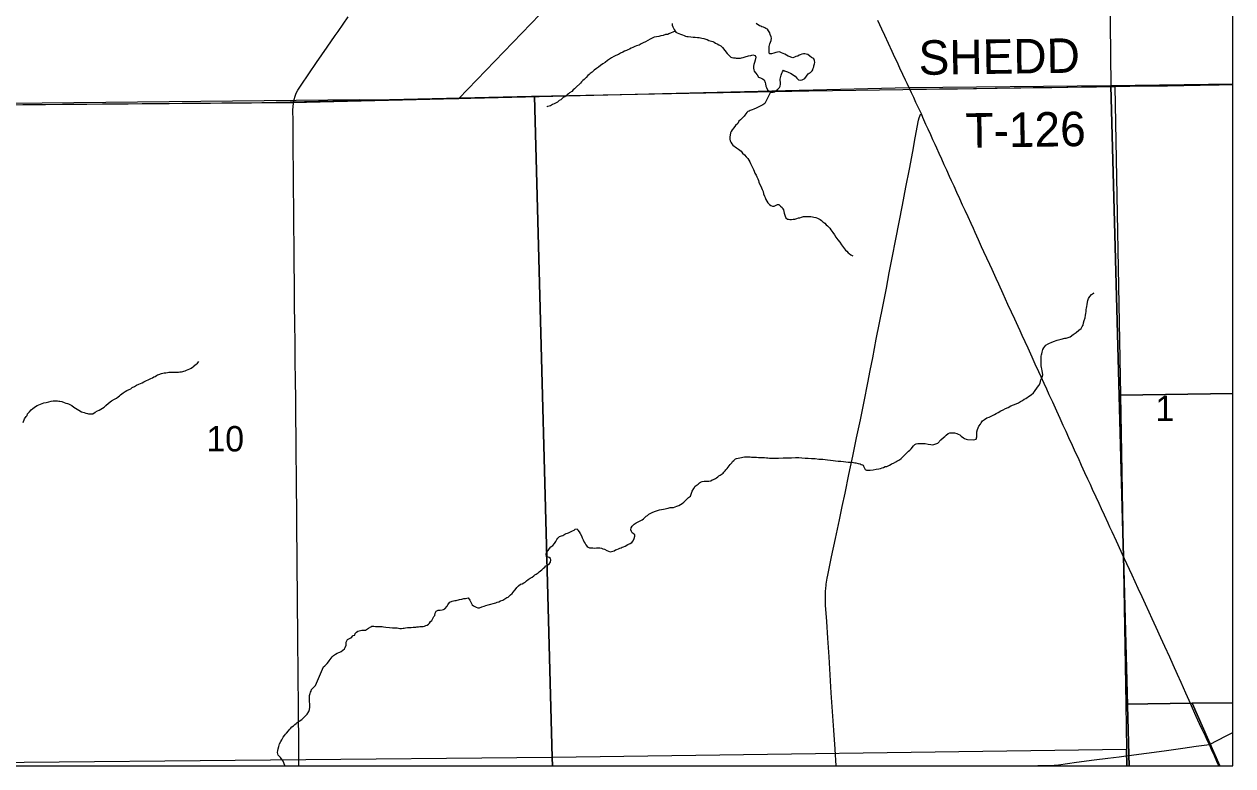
# Model space of a CAD drawing. Extents: x 103424 to 290657, y 38711 to 110967.
# Drawn here: x 165088 to 175680, y 38711 to 45205 of the extents above; entities that cross this region are included whole.
import ezdxf

# ---------------------------------------------------------------- set-up
doc = ezdxf.new("R2010")
doc.units = 0
for name, color, linetype in [('GM_X_Corporation', 7, 'Continuous'), ('GM_X_County_Road', 7, 'Continuous'), ('GM_X_Minor_Lake', 7, 'Continuous'), ('GM_X_Minor_River', 7, 'Continuous'), ('GM_X_Rail_Line', 7, 'Continuous'), ('GM_X_Section_Text', 7, 'Continuous'), ('GM_X_State_Route', 7, 'Continuous'), ('GM_X_Township_Road', 7, 'Continuous'), ('GM_X_Township_Road_Text', 7, 'Continuous')]:
    doc.layers.add(name, color=color, linetype=linetype)

msp = doc.modelspace()

# ---------------------------------------------------------------- linework, layer by layer
at = {"layer": 'GM_X_Corporation'}
for points in [[(103424, 96535), (103424, 38711), (175680, 38711), (175680, 110967), (119699, 110967), (119717, 106543), (119720, 106323), (119721, 106006), (119710, 99446), (119706, 99064), (119664, 96690), (117026, 96688), (115542, 96665), (105082, 96575)], [(175680, 44681), (175680, 72246), (175616, 72243), (174070, 72209), (174125, 69464), (174129, 69223), (174137, 68978), (174141, 68791), (174153, 68331), (174162, 67903), (174163, 67851), (174375, 58453), (174464, 53422), (174471, 52952), (174477, 52329), (174484, 51788), (174488, 51508), (174502, 50651), (174515, 49999), (174519, 49484), (174525, 49008), (174531, 48282), (174580, 47395), (174610, 44665)], [(149533, 38711), (174770, 38711), (174768, 38806), (174722, 40540), (174610, 44665), (172843, 44649), (172841, 44649), (167442, 44516), (162024, 44473), (156824, 44364), (149451, 44181), (149476, 42605), (149528, 39851)], [(174646, 44661), (174695, 41956), (174741, 39251), (174748, 38853), (169715, 38783), (169560, 44575), (171965, 44622)], [(174770, 38711), (175680, 38711), (175680, 44681), (174610, 44665), (174722, 40540), (174768, 38806)], [(175680, 41972), (175680, 44678), (174646, 44661), (174695, 41956)], [(169560, 44575), (169715, 38783), (164775, 38737), (164656, 44497), (164722, 44498), (167170, 44520), (169535, 44575)], [(175680, 39263), (175680, 41972), (174695, 41956), (174741, 39251), (175322, 39259)], [(174751, 38711), (175567, 38711), (175322, 39259), (174741, 39251), (174748, 38853)], [(175567, 38711), (175680, 38711), (175680, 39263), (175322, 39259)], [(164775, 38711), (169717, 38711), (169715, 38783), (164775, 38737)], [(169717, 38711), (174751, 38711), (174748, 38853), (169715, 38783)]]:
    msp.add_lwpolyline(points, close=True, dxfattribs=at)
msp.add_lwpolyline([(174163, 67851), (174375, 58453), (174464, 53422), (174471, 52952), (174477, 52329), (174484, 51788), (174488, 51508), (174502, 50651), (174515, 49999), (174519, 49484), (174525, 49008), (174531, 48282), (174580, 47395), (174610, 44665), (172843, 44649), (172841, 44649), (167442, 44516), (162024, 44473)], dxfattribs=at)
at = {"layer": 'GM_X_County_Road'}
for points in [[(167814, 45106), (167838, 45141), (167927, 45269)], [(167462, 44574), (167470, 44600), (167487, 44628), (167516, 44671), (167583, 44770), (167650, 44869), (167744, 45005), (167814, 45106)], [(167496, 38711), (167495, 38797), (167494, 38962), (167492, 39127), (167491, 39292), (167490, 39439), (167488, 39586), (167487, 39751), (167485, 39916), (167484, 40082), (167483, 40247), (167481, 40412), (167480, 40498), (167480, 40585), (167478, 40750), (167477, 40915), (167476, 41006), (167475, 41097), (167473, 41262), (167472, 41427), (167470, 41592), (167468, 41757), (167467, 41922), (167465, 42087), (167463, 42252), (167462, 42417), (167460, 42582), (167458, 42747), (167457, 42843), (167456, 42939), (167455, 43104), (167453, 43269), (167452, 43434), (167450, 43599), (167449, 43764), (167447, 43929), (167446, 44094), (167445, 44259), (167444, 44357), (167443, 44455), (167447, 44512), (167455, 44546), (167462, 44574)], [(172203, 38711), (172194, 38857), (172183, 39022), (172172, 39186), (172161, 39351), (172151, 39508), (172141, 39665), (172130, 39830), (172121, 39975), (172111, 40119), (172110, 40152), (172109, 40186), (172110, 40219), (172111, 40236), (172113, 40270), (172115, 40286), (172117, 40303), (172119, 40320), (172122, 40336), (172125, 40353), (172130, 40380), (172164, 40542), (172198, 40703), (172232, 40865), (172257, 40982), (172282, 41100), (172316, 41261), (172350, 41423), (172383, 41582), (172416, 41740), (172448, 41902), (172480, 42064), (172502, 42174), (172524, 42284), (172555, 42446), (172584, 42590), (172612, 42733), (172644, 42895), (172669, 43028), (172695, 43160), (172727, 43322), (172756, 43472), (172785, 43622), (172814, 43777), (172845, 43935), (172875, 44092), (172897, 44210), (172926, 44365), (172931, 44386), (172936, 44401), (172941, 44411), (172950, 44419)]]:
    msp.add_lwpolyline(points, dxfattribs=at)
at = {"layer": 'GM_X_Minor_Lake'}
for points in [[(170766, 45211), (170767, 45197), (170773, 45181), (170777, 45171), (170785, 45159), (170793, 45145), (170799, 45135), (170809, 45131), (170824, 45125), (170838, 45119), (170858, 45113), (170872, 45105), (170884, 45101), (170896, 45099), (170908, 45097), (170929, 45095), (170949, 45093), (170969, 45091)], [(171999, 44909), (171987, 44915), (171972, 44925), (171954, 44939), (171942, 44943), (171930, 44945), (171918, 44945), (171904, 44943), (171888, 44937), (171878, 44933), (171868, 44926), (171851, 44922), (171839, 44916), (171823, 44912), (171783, 44926), (171767, 44934), (171753, 44942), (171738, 44948), (171724, 44956), (171714, 44960), (171704, 44962), (171690, 44959), (171676, 44957), (171656, 44951), (171638, 44945), (171619, 44947), (171617, 44959), (171615, 44979), (171617, 44999), (171617, 45009), (171619, 45021), (171623, 45034), (171627, 45048), (171635, 45064), (171638, 45084), (171634, 45096), (171626, 45116), (171622, 45130), (171612, 45147), (171602, 45161), (171587, 45169), (171577, 45173), (171567, 45179), (171553, 45182), (171543, 45188), (171533, 45192), (171502, 45212)], [(170969, 45091), (170987, 45089), (171003, 45088), (171015, 45086), (171026, 45084), (171044, 45080), (171060, 45074), (171074, 45070), (171088, 45064), (171100, 45060), (171112, 45058), (171123, 45054), (171135, 45048), (171147, 45040), (171161, 45032), (171175, 45024), (171193, 45016), (171206, 45000), (171248, 44948), (171261, 44936), (171279, 44918), (171289, 44914), (171303, 44912), (171317, 44910), (171327, 44908), (171343, 44908), (171354, 44908), (171364, 44909), (171374, 44911), (171390, 44915), (171406, 44919), (171416, 44923), (171426, 44925), (171436, 44929), (171456, 44931), (171472, 44936), (171495, 44930), (171499, 44916), (171495, 44889), (171487, 44869), (171481, 44851), (171479, 44837), (171479, 44819), (171481, 44806), (171485, 44794), (171496, 44780), (171512, 44762), (171524, 44742), (171540, 44736), (171559, 44728), (171573, 44718), (171581, 44696), (171583, 44684), (171587, 44664), (171593, 44652), (171602, 44630), (171618, 44616), (171628, 44610), (171638, 44610), (171650, 44610), (171662, 44612), (171678, 44624), (171692, 44636), (171706, 44651), (171714, 44663), (171716, 44679), (171716, 44697), (171714, 44713), (171714, 44725), (171716, 44736), (171722, 44758), (171728, 44776), (171732, 44788), (171741, 44802), (171752, 44798), (171768, 44792), (171778, 44788), (171788, 44782), (171802, 44777), (171843, 44749), (171859, 44733), (171873, 44719), (171891, 44715), (171905, 44717), (171918, 44723), (171928, 44731), (171944, 44749), (171949, 44759), (171957, 44770), (171968, 44776), (171978, 44782), (171992, 44796), (171998, 44806), (172003, 44820), (172007, 44831), (172009, 44841), (172013, 44859), (172017, 44871), (172015, 44887), (172009, 44901), (171999, 44909)]]:
    msp.add_lwpolyline(points, dxfattribs=at)
at = {"layer": 'GM_X_Minor_River'}
for points in [[(170793, 45145), (170737, 45122), (170727, 45116), (170709, 45114), (170687, 45107), (170668, 45103), (170650, 45099), (170630, 45095), (170610, 45091), (170592, 45083), (170574, 45074), (170554, 45064), (170534, 45052), (170512, 45042), (170494, 45033), (170478, 45023), (170455, 45015), (170439, 45009), (170423, 45001), (170407, 44994), (170393, 44988), (170379, 44982), (170365, 44974), (170349, 44968), (170333, 44960), (170315, 44951), (170295, 44941), (170273, 44931), (170254, 44921), (170234, 44910), (170218, 44898), (170200, 44886), (170178, 44870), (170158, 44857), (170138, 44843), (170120, 44829), (170102, 44817), (170084, 44802), (170066, 44786), (170048, 44774), (170038, 44764), (170028, 44757), (170012, 44739), (170004, 44729), (169994, 44721), (169984, 44711), (169972, 44701), (169962, 44688), (169922, 44650), (169910, 44640), (169900, 44631), (169886, 44617), (169868, 44603), (169858, 44595), (169846, 44587), (169836, 44578), (169826, 44570), (169812, 44562), (169802, 44554), (169790, 44544), (169776, 44536), (169762, 44523), (169745, 44515), (169733, 44509), (169719, 44503), (169709, 44497), (169699, 44491), (169687, 44487), (169675, 44484), (169669, 44482), (169667, 44482)], [(171628, 44610), (171578, 44510), (171560, 44498), (171538, 44488), (171520, 44478), (171502, 44470), (171482, 44461), (171466, 44455), (171450, 44449), (171440, 44445), (171430, 44441), (171420, 44431), (171404, 44410), (171396, 44400), (171380, 44382), (171366, 44368), (171352, 44355), (171342, 44337), (171322, 44317), (171306, 44297), (171292, 44280), (171284, 44266), (171278, 44254), (171272, 44216), (171272, 44199), (171274, 44185), (171281, 44171), (171289, 44157), (171297, 44145), (171309, 44137), (171319, 44131), (171331, 44123), (171348, 44111), (171358, 44103), (171370, 44093), (171384, 44077), (171400, 44061), (171415, 44043), (171429, 44029), (171439, 44015), (171447, 44001), (171453, 43985), (171462, 43969), (171470, 43951), (171478, 43934), (171484, 43918), (171492, 43902), (171503, 43884), (171509, 43868), (171517, 43852), (171523, 43838), (171527, 43822), (171533, 43806), (171542, 43788), (171550, 43773), (171556, 43757), (171564, 43739), (171568, 43719), (171575, 43699), (171581, 43687), (171587, 43671), (171595, 43655), (171605, 43641), (171619, 43625), (171630, 43619), (171646, 43613), (171660, 43613), (171690, 43625), (171702, 43627), (171716, 43613), (171729, 43601), (171737, 43589), (171743, 43579), (171745, 43565), (171749, 43551), (171753, 43533), (171757, 43523), (171761, 43511), (171776, 43499), (171786, 43497), (171798, 43495), (171812, 43495), (171828, 43497), (171842, 43499), (171860, 43505), (171872, 43509), (171884, 43511), (171899, 43516), (171917, 43520), (171939, 43522), (171959, 43522), (171973, 43522), (171983, 43520), (171995, 43518), (172009, 43516), (172024, 43512)], [(172024, 43512), (172040, 43507), (172052, 43501), (172064, 43495), (172076, 43485), (172086, 43475), (172103, 43463), (172117, 43449), (172129, 43439), (172147, 43419), (172157, 43404), (172174, 43382), (172188, 43362), (172202, 43340), (172219, 43316), (172235, 43296), (172249, 43274), (172286, 43228), (172296, 43218), (172308, 43204), (172318, 43198), (172333, 43186), (172343, 43180), (172349, 43176)], [(173343, 41572), (173355, 41568), (173405, 41566), (173420, 41569), (173430, 41571), (173436, 41593), (173435, 41615), (173435, 41627), (173435, 41637), (173441, 41656), (173447, 41670), (173455, 41684), (173467, 41702), (173475, 41714), (173485, 41731), (173503, 41745), (173525, 41757), (173545, 41765), (173557, 41769), (173567, 41776), (173579, 41782), (173591, 41788), (173605, 41796), (173623, 41806), (173646, 41819), (173666, 41829), (173688, 41839), (173710, 41849), (173734, 41862), (173758, 41872), (173782, 41880), (173800, 41890), (173818, 41901), (173836, 41911), (173850, 41921), (173867, 41929), (173897, 41952), (173913, 41960), (173933, 41978), (173941, 41988), (173967, 42027), (173979, 42041), (173990, 42063), (173998, 42090), (174008, 42114), (174014, 42134), (174012, 42154), (174008, 42170), (174006, 42187), (174004, 42199), (174001, 42215), (174001, 42237), (173999, 42263), (173999, 42285), (174001, 42298), (174003, 42310), (174005, 42320), (174009, 42334), (174016, 42356), (174024, 42370), (174042, 42395), (174060, 42407), (174073, 42411), (174089, 42417), (174109, 42426), (174139, 42438), (174175, 42448), (174207, 42455), (174219, 42457), (174254, 42469), (174280, 42487), (174308, 42506), (174330, 42526), (174350, 42540), (174360, 42557), (174368, 42571), (174372, 42589), (174377, 42611), (174385, 42635), (174389, 42656), (174391, 42672), (174393, 42690), (174393, 42708), (174397, 42720), (174399, 42732), (174403, 42751), (174405, 42771), (174408, 42787), (174416, 42803), (174428, 42820), (174442, 42838), (174458, 42850), (174466, 42854)], [(166267, 42138), (166291, 42148), (166313, 42153), (166330, 42153), (166344, 42155), (166354, 42158), (166366, 42158), (166382, 42158), (166398, 42159), (166412, 42159), (166426, 42157), (166439, 42157), (166451, 42160), (166465, 42160), (166499, 42169), (166511, 42175), (166525, 42182), (166539, 42188), (166551, 42192), (166563, 42201), (166573, 42209), (166583, 42219), (166593, 42225), (166607, 42238), (166617, 42252)], [(165080, 41718), (165089, 41749), (165105, 41769), (165115, 41780), (165116, 41794), (165134, 41812), (165148, 41827), (165164, 41841), (165174, 41849), (165186, 41858), (165200, 41866), (165244, 41883), (165260, 41890), (165280, 41894), (165304, 41899), (165324, 41903), (165342, 41906), (165365, 41906), (165379, 41906), (165391, 41905), (165401, 41905), (165417, 41901), (165438, 41894), (165452, 41888), (165466, 41884), (165476, 41880), (165489, 41874), (165505, 41865), (165523, 41853), (165538, 41843), (165552, 41835), (165566, 41826), (165591, 41812), (165603, 41808), (165613, 41804), (165628, 41799), (165642, 41795), (165652, 41793), (165666, 41793), (165676, 41794), (165688, 41794), (165710, 41809), (165730, 41819), (165746, 41826), (165788, 41853), (165804, 41865), (165826, 41886), (165854, 41907), (165880, 41921), (165898, 41932), (165912, 41942), (165922, 41950), (165932, 41959), (165943, 41969), (165955, 41977), (165973, 41988), (165987, 41998), (166007, 42007), (166021, 42013), (166035, 42024), (166053, 42034), (166073, 42045), (166091, 42053), (166107, 42059), (166121, 42066), (166137, 42074), (166155, 42083), (166179, 42093), (166197, 42102), (166213, 42110), (166225, 42117), (166235, 42121), (166247, 42129), (166257, 42135), (166267, 42138)], [(171523, 41411), (171540, 41411), (171558, 41412), (171576, 41410), (171592, 41408), (171606, 41408), (171620, 41406), (171634, 41406), (171650, 41406), (171673, 41404), (171699, 41405), (171739, 41407), (171773, 41407), (171812, 41409), (171846, 41410), (171876, 41410), (171904, 41408), (171933, 41406), (171959, 41404), (171987, 41403), (172019, 41401), (172052, 41397), (172086, 41395), (172128, 41392), (172155, 41388), (172177, 41386), (172197, 41382), (172221, 41380), (172245, 41378), (172268, 41376), (172288, 41373), (172308, 41371), (172324, 41369), (172338, 41369), (172354, 41367), (172367, 41365), (172377, 41363), (172397, 41359), (172413, 41355), (172423, 41351), (172433, 41347), (172441, 41345), (172443, 41335), (172452, 41317), (172458, 41305), (172470, 41299), (172482, 41299), (172502, 41299), (172528, 41304), (172553, 41308), (172577, 41312), (172593, 41316), (172607, 41320), (172619, 41324), (172633, 41331), (172649, 41333), (172659, 41339), (172671, 41345), (172685, 41353), (172695, 41357), (172707, 41361), (172725, 41372), (172735, 41378), (172748, 41386), (172758, 41392), (172774, 41402), (172784, 41413), (172798, 41427), (172812, 41439), (172824, 41453), (172838, 41465), (172850, 41476), (172860, 41486), (172880, 41512), (172894, 41524), (172906, 41530), (172918, 41533), (172936, 41533), (172952, 41533), (172984, 41533), (173011, 41529), (173033, 41525), (173049, 41523), (173059, 41524), (173085, 41534), (173095, 41536), (173121, 41566), (173143, 41587), (173157, 41595), (173167, 41607), (173185, 41621), (173199, 41626), (173218, 41626), (173240, 41626), (173260, 41622), (173274, 41616), (173286, 41610), (173300, 41598), (173319, 41582), (173329, 41576), (173343, 41572)], [(170235, 40588), (170245, 40590), (170259, 40595), (170271, 40601), (170281, 40605), (170295, 40611), (170307, 40617), (170318, 40621), (170328, 40625), (170340, 40629), (170354, 40634), (170378, 40648), (170398, 40658), (170414, 40666), (170426, 40681), (170432, 40701), (170440, 40721), (170438, 40735), (170425, 40745), (170415, 40751), (170409, 40763), (170405, 40779), (170407, 40794), (170417, 40810), (170433, 40826), (170451, 40838), (170503, 40865), (170515, 40873), (170523, 40883), (170539, 40897), (170549, 40904), (170563, 40916), (170591, 40930), (170612, 40938), (170628, 40945), (170638, 40947), (170656, 40953), (170674, 40957), (170690, 40959), (170704, 40961), (170718, 40963), (170732, 40968), (170748, 40972), (170767, 40972), (170777, 40974), (170793, 40978), (170807, 40984), (170825, 40992), (170839, 40999), (170855, 41007), (170869, 41019), (170889, 41039), (170909, 41060), (170927, 41072), (170931, 41082), (170941, 41116), (170957, 41139), (170969, 41159), (170993, 41177), (171005, 41190), (171015, 41194), (171029, 41200), (171047, 41204), (171059, 41204), (171073, 41204), (171089, 41204), (171106, 41208), (171116, 41215), (171130, 41219), (171146, 41227), (171156, 41233), (171166, 41241), (171176, 41249), (171188, 41255), (171204, 41268), (171212, 41274), (171218, 41282), (171230, 41294), (171238, 41304), (171248, 41316), (171258, 41327), (171266, 41339), (171276, 41351), (171290, 41365), (171296, 41375), (171308, 41386), (171320, 41398), (171330, 41402), (171344, 41406), (171374, 41412), (171386, 41414), (171400, 41417), (171412, 41417), (171425, 41417), (171439, 41417), (171451, 41417), (171461, 41415), (171481, 41415), (171493, 41413), (171505, 41413), (171523, 41411)], [(168980, 40181), (168994, 40163), (168998, 40149), (169007, 40133), (169015, 40121), (169025, 40111), (169037, 40105), (169049, 40099), (169063, 40095), (169077, 40095), (169098, 40102), (169118, 40108), (169134, 40114), (169154, 40120), (169222, 40139), (169234, 40143), (169246, 40147), (169262, 40155), (169281, 40163), (169299, 40174), (169317, 40184), (169329, 40188), (169349, 40208), (169365, 40219), (169373, 40233), (169387, 40249), (169399, 40263), (169405, 40273), (169421, 40288), (169437, 40302), (169453, 40306), (169465, 40314), (169477, 40320), (169489, 40331), (169505, 40343), (169523, 40355), (169539, 40363), (169553, 40375), (169563, 40384), (169575, 40390), (169591, 40402), (169601, 40410), (169613, 40418), (169625, 40428), (169639, 40443), (169651, 40451), (169659, 40461), (169671, 40465), (169691, 40483), (169699, 40494), (169703, 40516), (169701, 40528), (169687, 40536), (169675, 40540), (169665, 40542), (169661, 40566), (169669, 40586), (169679, 40596), (169690, 40613), (169704, 40629), (169721, 40639), (169735, 40657), (169746, 40676), (169756, 40692), (169764, 40704), (169780, 40718), (169797, 40724), (169807, 40729), (169825, 40741), (169837, 40745), (169849, 40749), (169859, 40751), (169893, 40770), (169907, 40776), (169917, 40782), (169933, 40786), (169941, 40776), (169952, 40760), (169960, 40746), (169972, 40726), (169978, 40708), (169986, 40690), (169995, 40669), (170003, 40657), (170011, 40645), (170021, 40633), (170031, 40627), (170043, 40621), (170057, 40619), (170072, 40619), (170088, 40618), (170104, 40620), (170120, 40620), (170132, 40620), (170148, 40616), (170158, 40612), (170172, 40608), (170193, 40598), (170209, 40590), (170223, 40586), (170235, 40588)], [(167641, 39415), (167712, 39579), (167722, 39587), (167732, 39595), (167742, 39607), (167754, 39621), (167760, 39631), (167768, 39642), (167778, 39654), (167786, 39664), (167798, 39676), (167816, 39690), (167830, 39697), (167844, 39703), (167854, 39705), (167866, 39711), (167880, 39723), (167894, 39735), (167900, 39746), (167908, 39768), (167908, 39778), (167910, 39794), (167922, 39818), (167944, 39829), (167954, 39831), (167972, 39851), (167984, 39855), (167988, 39869), (168000, 39882), (168012, 39890), (168024, 39894), (168047, 39898), (168063, 39898), (168079, 39900), (168089, 39906), (168105, 39917), (168125, 39929), (168135, 39933), (168151, 39933), (168167, 39931), (168183, 39931), (168197, 39931), (168212, 39930), (168226, 39930), (168238, 39928), (168256, 39926), (168290, 39922), (168315, 39920), (168331, 39920), (168345, 39918), (168357, 39918), (168369, 39917), (168381, 39915), (168395, 39915), (168409, 39917), (168419, 39917), (168429, 39919), (168448, 39921), (168462, 39921), (168480, 39923), (168496, 39924), (168510, 39924), (168520, 39926), (168530, 39928), (168542, 39928), (168554, 39930), (168568, 39932), (168583, 39932), (168595, 39934), (168609, 39939), (168619, 39943), (168631, 39951), (168639, 39961), (168649, 39975), (168659, 39985), (168667, 39995), (168673, 40008), (168679, 40018), (168685, 40028), (168689, 40048), (168699, 40064), (168715, 40073), (168733, 40075), (168751, 40077), (168761, 40079), (168775, 40087), (168795, 40109), (168801, 40120), (168805, 40130), (168819, 40144), (168839, 40152), (168861, 40158), (168873, 40160), (168883, 40163), (168893, 40165), (168903, 40167), (168922, 40169), (168940, 40175), (168954, 40177), (168966, 40179), (168980, 40181)], [(167371, 38711), (167371, 38713), (167356, 38753), (167333, 38785), (167314, 38805), (167308, 38827), (167311, 38845), (167313, 38859), (167319, 38879), (167326, 38904), (167338, 38924), (167346, 38939), (167358, 38961), (167369, 38977), (167379, 38988), (167387, 38998), (167403, 39017), (167413, 39029), (167423, 39039), (167434, 39052), (167448, 39062), (167460, 39072), (167470, 39083), (167480, 39089), (167498, 39103), (167520, 39118), (167536, 39132), (167546, 39143), (167558, 39155), (167567, 39163), (167583, 39186), (167589, 39204), (167592, 39225), (167590, 39249), (167587, 39277), (167587, 39291), (167587, 39309), (167588, 39327), (167594, 39344), (167598, 39356), (167602, 39366), (167607, 39378), (167619, 39393), (167629, 39403), (167641, 39415)]]:
    msp.add_lwpolyline(points, dxfattribs=at)
at = {"layer": 'GM_X_Rail_Line'}
msp.add_lwpolyline([(146505, 45438), (151249, 45326), (154444, 45236), (154715, 45193), (154904, 45113), (155904, 44439), (156035, 44384), (156194, 44362), (156810, 44362), (161178, 44482), (161906, 44481), (168026, 44547), (168178, 44543), (168898, 44556), (171104, 46845), (171364, 47126), (171452, 47389), (171481, 47647), (171393, 47916), (171381, 48056), (171405, 48168), (171499, 48308), (174524, 51299), (175680, 52377)], dxfattribs=at)
at = {"layer": 'GM_X_State_Route'}
for points in [[(172849, 44637), (172827, 44685), (172812, 44716), (172789, 44764), (172762, 44821), (172737, 44875), (172718, 44914), (172694, 44966), (172662, 45036), (172630, 45105), (172603, 45163), (172569, 45238)], [(174676, 40645), (174660, 40679), (174622, 40759), (174603, 40801), (174586, 40836), (174554, 40906), (174528, 40962), (174507, 41009), (174481, 41065), (174451, 41131), (174431, 41174), (174410, 41220), (174384, 41277), (174355, 41340), (174326, 41404), (174302, 41456), (174274, 41517), (174244, 41583), (174219, 41638), (174194, 41691), (174166, 41752), (174136, 41817), (174101, 41895), (174071, 41961), (174049, 42009), (174025, 42060), (173999, 42118), (173979, 42160), (173948, 42229), (173920, 42289), (173886, 42368), (173860, 42423), (173835, 42478), (173816, 42520), (173799, 42558), (173770, 42621), (173741, 42683), (173709, 42752), (173688, 42797), (173666, 42845), (173628, 42929), (173605, 42978), (173571, 43056), (173549, 43101), (173524, 43157), (173498, 43213), (173478, 43257), (173451, 43316), (173421, 43382), (173406, 43416), (173386, 43459), (173360, 43517), (173334, 43573), (173312, 43622), (173287, 43677), (173262, 43732), (173237, 43786), (173215, 43834), (173197, 43873), (173173, 43927), (173151, 43975), (173129, 44024), (173106, 44073), (173085, 44119), (173070, 44153), (173051, 44193), (173032, 44236), (173009, 44287), (172990, 44327), (172963, 44387), (172950, 44419), (172918, 44484), (172902, 44519), (172883, 44562), (172864, 44605), (172849, 44637)], [(175558, 38711), (175541, 38749), (175518, 38799), (175494, 38854), (175474, 38897), (175456, 38936), (175439, 38971), (175412, 39029), (175388, 39080), (175359, 39144), (175326, 39217), (175296, 39284), (175268, 39348), (175226, 39442), (175195, 39512), (175158, 39594), (175127, 39662), (175084, 39755), (175048, 39833), (175007, 39923), (174973, 39998), (174946, 40056), (174914, 40126), (174884, 40192), (174850, 40265), (174824, 40321), (174797, 40380), (174774, 40431), (174751, 40479), (174714, 40562), (174676, 40645)]]:
    msp.add_lwpolyline(points, dxfattribs=at)
at = {"layer": 'GM_X_Township_Road'}
msp.add_line((174683, 38790), (174704, 38793), dxfattribs=at)
for points in [[(172849, 44637), (173108, 44639), (173268, 44640), (173433, 44643), (173598, 44645), (173764, 44648), (173929, 44650), (174094, 44652), (174224, 44654), (174355, 44656), (174484, 44658), (174613, 44660)], [(174613, 44660), (174778, 44662), (174943, 44665), (175108, 44667), (175193, 44669)], [(175193, 44669), (175251, 44669), (175394, 44672), (175559, 44674), (175662, 44676), (175680, 44676)], [(175474, 38897), (175621, 38974), (175680, 39004)], [(174704, 38793), (174769, 38801), (174924, 38822), (175078, 38843), (175241, 38866), (175358, 38882), (175474, 38897)], [(173859, 38711), (173865, 38711), (173970, 38713), (174076, 38714), (174153, 38721), (174309, 38742), (174464, 38763), (174584, 38778), (174683, 38790)]]:
    msp.add_lwpolyline(points, dxfattribs=at)

# ---------------------------------------------------------------- texts
at = {"layer": 'GM_X_Section_Text'}
for s, height, p in [('1', 222, (175001, 41730)), ('10', 222.4, (166684, 41464))]:
    msp.add_text(s, height=height, rotation=0, dxfattribs=at).set_placement(p)
at = {"layer": 'GM_X_Township_Road_Text'}
for s, rotation, p in [('SHEDD', 0.8252, (172928, 44761)), ('T-126', 0.8421, (173338, 44123))]:
    msp.add_text(s, height=301.9, rotation=rotation, dxfattribs=at).set_placement(p)

doc.saveas('drawing.dxf')
